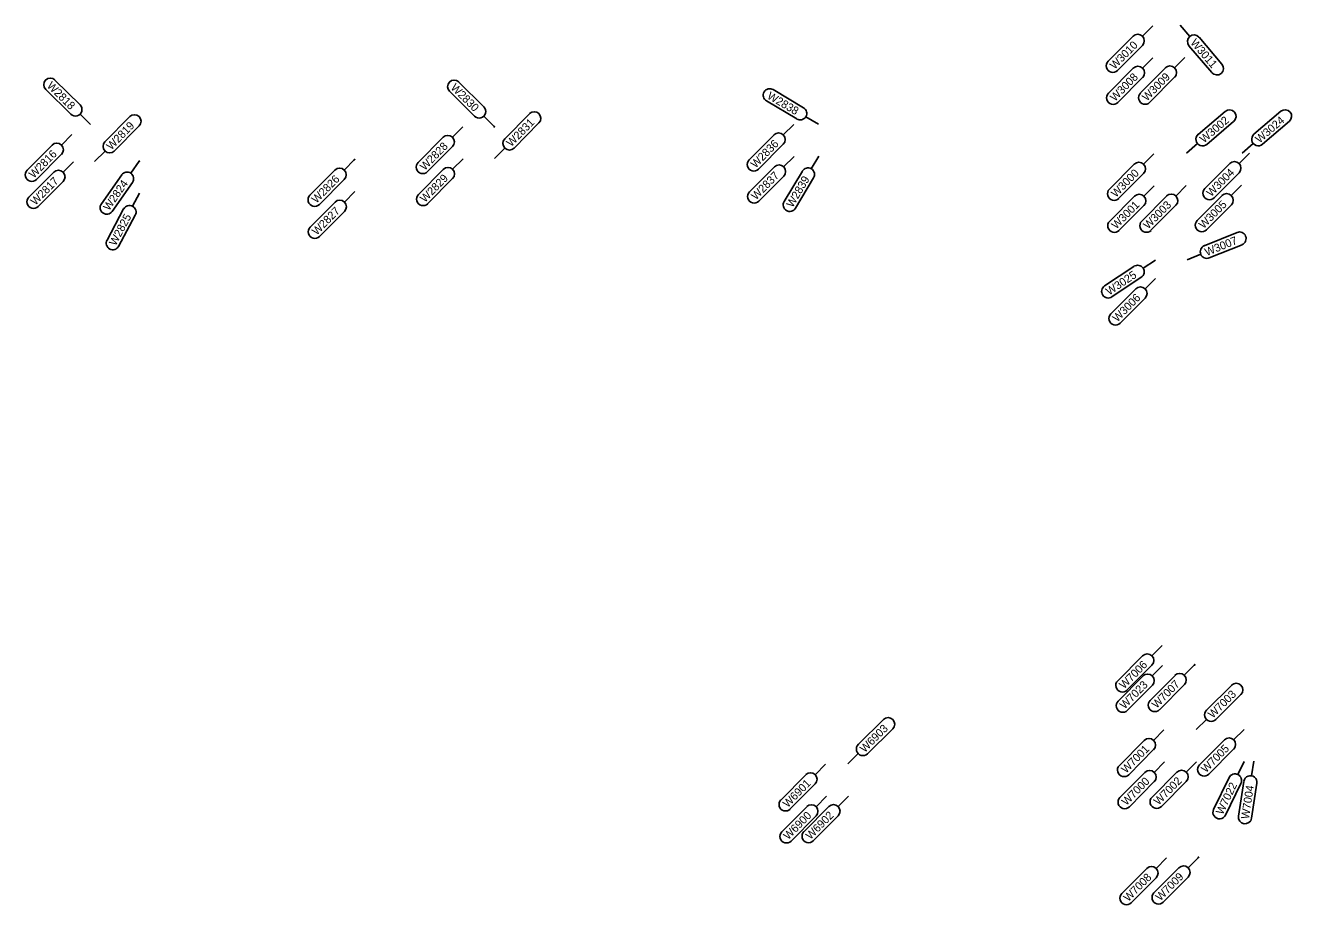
# Model space of a CAD drawing. Extents: x 12479652 to 12487250, y 9842710 to 9846560.
# Drawn here: x 12484888 to 12485085.8, y 9842743 to 9842880.4 of the extents above; entities that cross this region are included whole.
import ezdxf

# ---------------------------------------------------------------- set-up
doc = ezdxf.new("R2010")
doc.units = 0
doc.layers.add('_CIVIL_CONSTRUCTION', color=7, linetype='Continuous')
doc.layers.add('TextAlignmentLrg', color=7, linetype='Continuous')

msp = doc.modelspace()

# ---------------------------------------------------------------- linework, layer by layer
at = {"layer": '_CIVIL_CONSTRUCTION'}
for p, q in [((12485064.08, 9842880.3), (12485062.46, 9842878.67)), ((12485068.37, 9842880.36), (12485069.86, 9842878.61)), ((12485057.12, 9842874.75), (12485061.01, 9842878.66)), ((12485062.47, 9842877.22), (12485058.58, 9842873.3)), ((12485069.74, 9842877.16), (12485073.33, 9842872.97)), ((12485074.89, 9842874.3), (12485071.31, 9842878.49)), ((12485064.12, 9842875.3), (12485062.5, 9842873.67)), ((12485069.12, 9842875.34), (12485067.5, 9842873.7)), ((12485057.16, 9842869.75), (12485061.05, 9842873.66)), ((12485062.16, 9842869.79), (12485066.05, 9842873.7)), ((12484892.64, 9842871.81), (12484896.56, 9842867.92)), ((12484955.7, 9842871.5), (12484959.61, 9842867.61)), ((12485062.5, 9842872.22), (12485058.61, 9842868.3)), ((12485067.5, 9842872.25), (12485063.61, 9842868.34)), ((12484895.11, 9842866.47), (12484891.2, 9842870.36)), ((12484958.16, 9842866.16), (12484954.25, 9842870.05)), ((12485004.8, 9842870.31), (12485009.55, 9842867.49)), ((12485008.5, 9842865.73), (12485003.76, 9842868.55)), ((12484898.19, 9842864.85), (12484896.56, 9842866.47)), ((12484904.32, 9842866.1), (12484900.45, 9842862.17)), ((12484961.25, 9842864.54), (12484959.62, 9842866.16)), ((12484966.76, 9842866.56), (12484962.89, 9842862.63)), ((12484964.35, 9842861.19), (12484968.22, 9842865.12)), ((12485011.88, 9842864.91), (12485009.91, 9842866.09)), ((12485075.39, 9842866.91), (12485071.19, 9842863.33)), ((12485072.52, 9842861.77), (12485076.72, 9842865.35)), ((12485084.09, 9842866.93), (12485079.89, 9842863.35)), ((12485081.22, 9842861.79), (12485085.42, 9842865.37)), ((12484895.27, 9842863.29), (12484893.65, 9842861.66)), ((12484901.91, 9842860.73), (12484905.78, 9842864.65)), ((12484956.34, 9842864.5), (12484954.72, 9842862.87)), ((12485001.05, 9842859.33), (12485004.94, 9842863.25)), ((12485008.01, 9842864.88), (12485006.39, 9842863.25)), ((12484888.31, 9842857.74), (12484892.2, 9842861.65)), ((12484949.38, 9842858.95), (12484953.27, 9842862.87)), ((12484954.72, 9842861.42), (12484950.83, 9842857.51)), ((12484961.28, 9842859.54), (12484962.9, 9842861.18)), ((12485006.39, 9842861.8), (12485002.5, 9842857.89)), ((12485069.33, 9842860.39), (12485071.08, 9842861.88)), ((12485078.03, 9842860.41), (12485079.78, 9842861.9)), ((12484893.66, 9842860.21), (12484889.77, 9842856.29)), ((12484898.84, 9842859.08), (12484900.46, 9842860.72)), ((12484905.81, 9842859.13), (12484904.48, 9842857.25)), ((12484939.43, 9842859.38), (12484937.81, 9842857.75)), ((12484956.37, 9842859.5), (12484954.75, 9842857.87)), ((12485008.06, 9842859.88), (12485006.44, 9842858.25)), ((12485011.94, 9842859.91), (12485010.76, 9842857.94)), ((12485064.27, 9842860.3), (12485062.65, 9842858.67)), ((12485079.18, 9842860.41), (12485077.56, 9842858.78)), ((12484888.57, 9842853.5), (12484892.46, 9842857.42)), ((12484895.53, 9842859.05), (12484893.91, 9842857.42)), ((12484932.47, 9842853.83), (12484936.36, 9842857.74)), ((12484949.41, 9842853.95), (12484953.3, 9842857.87)), ((12485001.1, 9842854.34), (12485004.99, 9842858.25)), ((12485006.53, 9842852.84), (12485009.36, 9842857.58)), ((12485057.31, 9842854.75), (12485061.2, 9842858.66)), ((12485062.65, 9842857.22), (12485058.76, 9842853.3)), ((12485072.22, 9842854.86), (12485076.11, 9842858.77)), ((12485077.56, 9842857.33), (12485073.67, 9842853.41)), ((12484893.92, 9842855.97), (12484890.03, 9842852.06)), ((12484899.89, 9842852.48), (12484903.06, 9842856.99)), ((12484904.74, 9842855.82), (12484901.56, 9842851.3)), ((12484937.82, 9842856.29), (12484933.93, 9842852.38)), ((12484954.75, 9842856.42), (12484950.86, 9842852.51)), ((12485006.45, 9842856.8), (12485002.56, 9842852.89)), ((12485011.12, 9842856.53), (12485008.29, 9842851.79)), ((12485064.32, 9842855.3), (12485062.7, 9842853.67)), ((12485069.32, 9842855.34), (12485067.7, 9842853.7)), ((12485077.97, 9842855.4), (12485076.35, 9842853.77)), ((12484905.84, 9842854.13), (12484904.76, 9842852.1)), ((12484939.47, 9842854.38), (12484937.85, 9842852.75)), ((12485057.36, 9842849.75), (12485061.25, 9842853.66)), ((12485062.36, 9842849.79), (12485066.25, 9842853.7)), ((12485071.01, 9842849.85), (12485074.9, 9842853.76)), ((12484900.77, 9842846.81), (12484903.37, 9842851.68)), ((12484932.51, 9842848.83), (12484936.4, 9842852.74)), ((12484937.85, 9842851.29), (12484933.96, 9842847.38)), ((12485062.7, 9842852.22), (12485058.81, 9842848.3)), ((12485067.7, 9842852.25), (12485063.81, 9842848.34)), ((12485076.36, 9842852.32), (12485072.47, 9842848.41)), ((12484905.18, 9842850.71), (12484902.58, 9842845.84)), ((12485077.26, 9842848.01), (12485072.14, 9842845.94)), ((12485072.91, 9842844.04), (12485078.03, 9842846.1)), ((12485064.49, 9842843.7), (12485062.57, 9842842.43)), ((12485069.44, 9842843.74), (12485071.58, 9842844.61)), ((12485056.56, 9842839.66), (12485061.15, 9842842.71)), ((12485062.29, 9842841.01), (12485057.69, 9842837.95)), ((12485064.52, 9842840.84), (12485062.89, 9842839.21)), ((12485057.55, 9842835.29), (12485061.44, 9842839.21)), ((12485062.9, 9842837.76), (12485059.01, 9842833.85)), ((12485065.57, 9842783.52), (12485063.95, 9842781.89)), ((12485058.61, 9842777.97), (12485062.5, 9842781.88)), ((12485063.95, 9842780.44), (12485060.06, 9842776.52)), ((12485065.63, 9842780.37), (12485064.01, 9842778.74)), ((12485070.63, 9842780.47), (12485069.01, 9842778.84)), ((12485058.67, 9842774.82), (12485062.56, 9842778.73)), ((12485063.67, 9842774.92), (12485067.56, 9842778.83)), ((12485064.02, 9842777.29), (12485060.13, 9842773.37)), ((12485069.02, 9842777.39), (12485065.13, 9842773.47)), ((12485076.41, 9842777.29), (12485072.48, 9842773.41)), ((12485073.92, 9842771.95), (12485077.85, 9842775.83)), ((12485022.03, 9842771.94), (12485018.11, 9842768.06)), ((12485019.55, 9842766.6), (12485023.48, 9842770.48)), ((12485065.84, 9842770.31), (12485064.21, 9842768.68)), ((12485070.84, 9842770.35), (12485072.47, 9842771.96)), ((12485078.34, 9842770.4), (12485076.72, 9842768.77)), ((12485058.87, 9842764.76), (12485062.76, 9842768.67)), ((12485071.38, 9842764.85), (12485075.27, 9842768.77)), ((12485016.46, 9842764.99), (12485018.1, 9842766.61)), ((12485064.22, 9842767.23), (12485060.33, 9842763.31)), ((12485076.72, 9842767.32), (12485072.83, 9842763.41)), ((12485012.99, 9842764.95), (12485011.37, 9842763.32)), ((12485065.94, 9842765.31), (12485064.31, 9842763.68)), ((12485070.94, 9842765.35), (12485069.31, 9842763.72)), ((12485078.38, 9842765.4), (12485077.37, 9842763.33)), ((12485079.85, 9842765.41), (12485079.5, 9842763.14)), ((12485006.03, 9842759.41), (12485009.92, 9842763.32)), ((12485058.97, 9842759.76), (12485062.86, 9842763.67)), ((12485064.32, 9842762.23), (12485060.43, 9842758.32)), ((12485063.97, 9842759.8), (12485067.86, 9842763.71)), ((12485069.32, 9842762.27), (12485065.43, 9842758.35)), ((12485073.59, 9842757.9), (12485076, 9842762.86)), ((12485077.49, 9842756.83), (12485078.33, 9842762.28)), ((12485011.37, 9842761.87), (12485007.48, 9842757.96)), ((12485077.85, 9842761.96), (12485075.44, 9842757)), ((12485080.35, 9842761.97), (12485079.51, 9842756.52)), ((12485006.16, 9842754.41), (12485010.05, 9842758.32)), ((12485009.62, 9842754.43), (12485013.5, 9842758.35)), ((12485013.12, 9842759.96), (12485011.5, 9842758.32)), ((12485016.58, 9842759.98), (12485014.96, 9842758.35)), ((12485011.5, 9842756.87), (12485007.61, 9842752.96)), ((12485014.96, 9842756.9), (12485011.07, 9842752.99)), ((12485066.23, 9842750.31), (12485064.61, 9842748.68)), ((12485071.23, 9842750.41), (12485069.61, 9842748.78)), ((12485059.27, 9842744.77), (12485063.16, 9842748.68)), ((12485064.27, 9842744.86), (12485068.16, 9842748.78)), ((12485064.62, 9842747.23), (12485060.73, 9842743.32)), ((12485069.62, 9842747.33), (12485065.73, 9842743.42))]:
    msp.add_line(p, q, dxfattribs=at)
for centre, start, end in [((12485061.74, 9842877.94), 315.1702, 135.1702), ((12485070.52, 9842877.83), 40.4712, 220.4712), ((12485057.85, 9842874.03), 135.1702, 315.1702), ((12485061.78, 9842872.94), 315.1702, 135.1702), ((12485066.78, 9842872.98), 315.1702, 135.1702), ((12485074.11, 9842873.63), 220.4712, 40.4712), ((12484891.92, 9842871.09), 45.1702, 225.1702), ((12484954.98, 9842870.78), 45.1702, 225.1702), ((12485004.28, 9842869.43), 59.3073, 239.3073), ((12485057.89, 9842869.03), 135.1702, 315.1702), ((12485062.89, 9842869.06), 135.1702, 315.1702), ((12484895.83, 9842867.2), 225.1702, 45.1702), ((12484958.89, 9842866.89), 225.1702, 45.1702), ((12485009.02, 9842866.61), 239.3073, 59.3073), ((12485076.06, 9842866.13), 310.4712, 130.4712), ((12485084.75, 9842866.15), 310.4712, 130.4712), ((12484905.05, 9842865.37), 315.3788, 135.3788), ((12484967.49, 9842865.84), 315.3788, 135.3788), ((12484953.99, 9842862.14), 315.1702, 135.1702), ((12485005.66, 9842862.52), 315.1702, 135.1702), ((12485071.86, 9842862.55), 130.4712, 310.4712), ((12485080.56, 9842862.57), 130.4712, 310.4712), ((12484892.93, 9842860.93), 315.1702, 135.1702), ((12484901.18, 9842861.45), 135.3788, 315.3788), ((12484963.62, 9842861.91), 135.3788, 315.3788), ((12485001.77, 9842858.61), 135.1702, 315.1702), ((12485076.83, 9842858.05), 315.1702, 135.1702), ((12484889.04, 9842857.02), 135.1702, 315.1702), ((12484893.19, 9842856.69), 315.1702, 135.1702), ((12484903.9, 9842856.41), 324.9292, 144.9292), ((12484937.09, 9842857.02), 315.1702, 135.1702), ((12484950.1, 9842858.23), 135.1702, 315.1702), ((12484954.02, 9842857.14), 315.1702, 135.1702), ((12485005.72, 9842857.52), 315.1702, 135.1702), ((12485010.24, 9842857.06), 329.2015, 149.2015), ((12485061.93, 9842857.94), 315.1702, 135.1702), ((12484889.3, 9842852.78), 135.1702, 315.1702), ((12484933.2, 9842853.1), 135.1702, 315.1702), ((12484950.13, 9842853.23), 135.1702, 315.1702), ((12485001.83, 9842853.61), 135.1702, 315.1702), ((12485058.04, 9842854.03), 135.1702, 315.1702), ((12485061.98, 9842852.94), 315.1702, 135.1702), ((12485066.97, 9842852.98), 315.1702, 135.1702), ((12485072.95, 9842854.14), 135.1702, 315.1702), ((12485075.63, 9842853.04), 315.1702, 135.1702), ((12484900.73, 9842851.89), 144.9292, 324.9292), ((12484904.28, 9842851.19), 331.8848, 151.8848), ((12484937.12, 9842852.02), 315.1702, 135.1702), ((12485007.41, 9842852.32), 149.2015, 329.2015), ((12485058.09, 9842849.03), 135.1702, 315.1702), ((12485063.09, 9842849.06), 135.1702, 315.1702), ((12485071.74, 9842849.13), 135.1702, 315.1702), ((12484933.24, 9842848.1), 135.1702, 315.1702), ((12485077.64, 9842847.06), 291.9939, 111.9939), ((12484901.68, 9842846.33), 151.8848, 331.8848), ((12485072.53, 9842844.99), 111.9939, 291.9939), ((12485061.72, 9842841.86), 303.6534, 123.6534), ((12485057.13, 9842838.8), 123.6534, 303.6534), ((12485062.17, 9842838.48), 315.1702, 135.1702), ((12485058.28, 9842834.57), 135.1702, 315.1702), ((12485063.23, 9842781.16), 315.1702, 135.1702), ((12485063.29, 9842778.01), 315.1702, 135.1702), ((12485068.29, 9842778.11), 315.1702, 135.1702), ((12485059.34, 9842777.25), 135.1702, 315.1702), ((12485077.13, 9842776.56), 314.6453, 134.6453), ((12485059.4, 9842774.1), 135.1702, 315.1702), ((12485064.4, 9842774.2), 135.1702, 315.1702), ((12485022.75, 9842771.21), 314.6453, 134.6453), ((12485073.2, 9842772.68), 134.6453, 314.6453), ((12485063.49, 9842767.95), 315.1702, 135.1702), ((12485076, 9842768.04), 315.1702, 135.1702), ((12485018.83, 9842767.33), 134.6453, 314.6453), ((12485059.6, 9842764.04), 135.1702, 315.1702), ((12485072.11, 9842764.13), 135.1702, 315.1702), ((12485010.64, 9842762.6), 315.1702, 135.1702), ((12485063.59, 9842762.95), 315.1702, 135.1702), ((12485068.59, 9842762.99), 315.1702, 135.1702), ((12485076.93, 9842762.41), 334.0996, 154.0996), ((12485079.34, 9842762.13), 351.2417, 171.2417), ((12485006.75, 9842758.68), 135.1702, 315.1702), ((12485010.77, 9842757.6), 315.1702, 135.1702), ((12485014.23, 9842757.62), 315.1702, 135.1702), ((12485059.7, 9842759.04), 135.1702, 315.1702), ((12485064.7, 9842759.08), 135.1702, 315.1702), ((12485074.52, 9842757.45), 154.0996, 334.0996), ((12485078.5, 9842756.67), 171.2417, 351.2417), ((12485006.88, 9842753.68), 135.1702, 315.1702), ((12485010.34, 9842753.71), 135.1702, 315.1702), ((12485063.89, 9842747.95), 315.1702, 135.1702), ((12485068.89, 9842748.05), 315.1702, 135.1702), ((12485060, 9842744.04), 135.1702, 315.1702), ((12485065, 9842744.14), 135.1702, 315.1702)]:
    msp.add_arc(centre, 1.03, start, end, dxfattribs=at)
at = {"layer": 'TextAlignmentLrg'}
for centre in [(12484961.25, 9842864.54), (12484905.81, 9842859.13), (12484939.43, 9842859.38), (12485070.63, 9842780.47), (12485071.23, 9842750.41)]:
    msp.add_circle(centre, 0.05, dxfattribs=at)

# ---------------------------------------------------------------- texts
at = {"layer": '_CIVIL_CONSTRUCTION'}
for s, rotation, p in [('W3010', 45.1702, (12485058.12, 9842873.4)), ('W3011', 310.4712, (12485069.89, 9842877.59)), ('W2818', 315.1702, (12484891.29, 9842870.81)), ('W2830', 315.1702, (12484954.35, 9842870.51)), ('W3008', 45.1702, (12485058.16, 9842868.4)), ('W3009', 45.1702, (12485063.16, 9842868.44)), ('W2838', 329.3073, (12485003.76, 9842869)), ('W2819', 45.3788, (12484901.43, 9842860.8)), ('W2831', 45.3788, (12484963.9, 9842861.3)), ('W3002', 40.4712, (12485072.08, 9842861.9)), ('W3024', 40.4712, (12485080.75, 9842861.89)), ('W2828', 45.1702, (12484950.38, 9842857.6)), ('W2836', 45.1702, (12485002.04, 9842857.98)), ('W2816', 45.1702, (12484889.31, 9842856.39)), ('W2837', 45.1702, (12485002.11, 9842853)), ('W3000', 45.1702, (12485058.31, 9842853.4)), ('W3004', 45.1702, (12485073.21, 9842853.5)), ('W2817', 45.1702, (12484889.58, 9842852.16)), ('W2824', 54.9292, (12484901.09, 9842851.31)), ('W2826', 45.1702, (12484933.47, 9842852.47)), ('W2829', 45.1702, (12484950.41, 9842852.6)), ('W2839', 59.2015, (12485007.84, 9842851.8)), ('W2827', 45.1702, (12484933.52, 9842847.49)), ('W3001', 45.1702, (12485058.39, 9842848.44)), ('W3003', 45.1702, (12485063.36, 9842848.44)), ('W3005', 45.1702, (12485072.02, 9842848.51)), ('W2825', 61.8848, (12484902.13, 9842845.82)), ('W3007', 21.9939, (12485072.51, 9842844.3)), ('W3025', 33.6534, (12485057.28, 9842838.14)), ('W3006', 45.1702, (12485058.55, 9842833.94)), ('W7006', 45.1702, (12485059.61, 9842776.62)), ('W7007', 45.1702, (12485064.68, 9842773.58)), ('W7023', 45.1702, (12485059.68, 9842773.48)), ('W7003', 44.6453, (12485073.45, 9842772.04)), ('W6903', 44.6453, (12485019.08, 9842766.69)), ('W7001', 45.1702, (12485059.91, 9842763.45)), ('W7005', 45.1702, (12485072.39, 9842763.52)), ('W6901', 45.1702, (12485007.06, 9842758.09)), ('W7000', 45.1702, (12485059.97, 9842758.41)), ('W7002', 45.1702, (12485064.99, 9842758.47)), ('W7022', 64.0996, (12485074.99, 9842756.97)), ('W7004', 81.2417, (12485079.09, 9842756.32)), ('W6900', 45.1702, (12485007.16, 9842753.06)), ('W6902', 45.1702, (12485010.63, 9842753.1)), ('W7008', 45.1702, (12485060.27, 9842743.41)), ('W7009', 45.1702, (12485065.27, 9842743.52))]:
    msp.add_text(s, height=1.25, rotation=rotation, dxfattribs=at).set_placement(p)

doc.saveas('drawing.dxf')
